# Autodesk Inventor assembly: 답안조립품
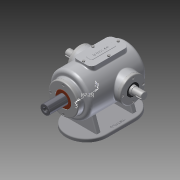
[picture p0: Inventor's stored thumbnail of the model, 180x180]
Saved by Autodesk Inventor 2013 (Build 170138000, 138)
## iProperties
Created: 2016-08
Part Number: 답안조립품
Document SubType Name: Assembly
Designer: Administrator
Mass: 8008.97 g
Surface Area: 4315.54 cm^2
Volume: 1881.21 cm^3
Density: 4.25734 g/cm^3
Author: Administrator
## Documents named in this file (16)
- C:\Users\Administrator\Desktop\360808V1016\답안조립품.iam
- C:\Users\Administrator\Desktop\360808V1016\본체.ipt
- C:\Users\Administrator\Desktop\360808V1016\베어링 6205.ipt
- 베어링 6205.ipt
- C:\Users\Administrator\Desktop\360808V1016\볼트 M4x0.7.ipt
- C:\Users\Administrator\Desktop\360808V1016\부시.ipt
- C:\Users\Administrator\Desktop\360808V1016\상부커버.ipt
- C:\Users\Administrator\Desktop\360808V1016\스프링.ipt
- C:\Users\Administrator\Desktop\360808V1016\슬라이드 커버.ipt
- C:\Users\Administrator\Desktop\360808V1016\슬라이드.ipt
- C:\Users\Administrator\Desktop\360808V1016\오일실.ipt
- 오일실.ipt
- C:\Users\Administrator\Desktop\360808V1016\육각머리볼트 M4.ipt
- C:\Users\Administrator\Desktop\360808V1016\축 커버.ipt
- C:\Users\Administrator\Desktop\360808V1016\편심축.ipt
- C:\Users\Administrator\Desktop\360808V1016\플레이트.ipt
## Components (13 placed, 2 different names)
1. 플레이트:1
2. M4x0.7:2
3. M4x0.7:4
4. M4x0.7:5
5. M4x0.7:6
6. M4x0.7:3
7. M4x0.7:7
8. M4x0.7:8
9. M4x0.7:9
10. M4x0.7:1
11. M4x0.7:10
12. M4x0.7:11
13. M4x0.7:12
